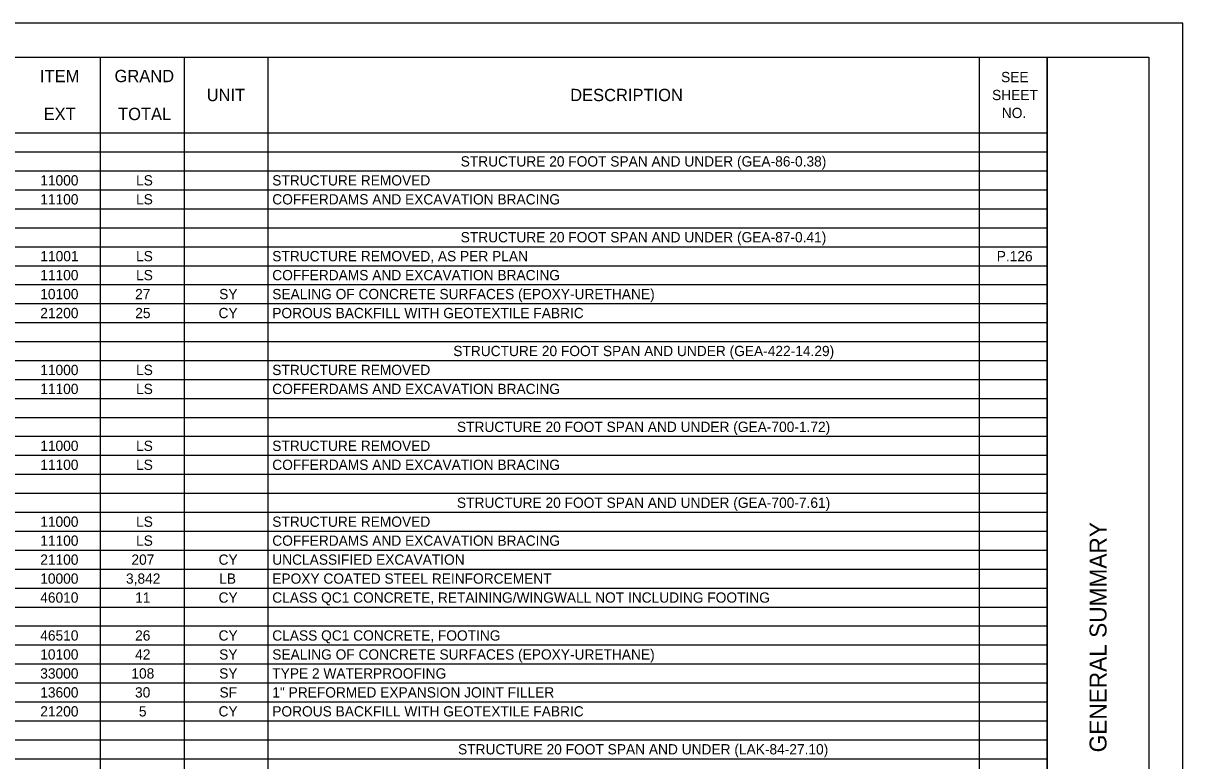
# Model space of a CAD drawing. Extents: x 0 to 34, y 0 to 22.
# Drawn here: x 16.9 to 34, y 11.11 to 22 of the extents above; entities that cross this region are included whole.
import ezdxf

# ---------------------------------------------------------------- set-up
doc = ezdxf.new("R2010")
doc.units = 0
for name, color, linetype in [('SH_Border', 7, 'Continuous'), ('SH_Cut_Line', 7, 'Continuous'), ('SH_Data', 7, 'Continuous'), ('SH_Text', 7, 'Continuous')]:
    doc.layers.add(name, color=color, linetype=linetype)

msp = doc.modelspace()

# ---------------------------------------------------------------- linework, layer by layer
at = {"layer": 'SH_Border'}
msp.add_line((32, 0.5), (32, 21.5), dxfattribs=at)
msp.add_lwpolyline([(1.5, 21.5), (33.5, 21.5), (33.5, 0.5), (1.5, 0.5)], close=True, dxfattribs=at)
at = {"layer": 'SH_Cut_Line'}
msp.add_lwpolyline([(0, 0), (34, 0), (34, 22), (0, 22)], close=True, dxfattribs=at)
at = {"layer": 'SH_Text'}
for p, q in [((1.5, 21.5), (32, 21.5)), ((18.035, 21.5), (18.035, 0.502)), ((19.27, 21.5), (19.27, 0.502)), ((20.505, 21.5), (20.505, 0.502)), ((30.995, 21.5), (30.995, 0.502)), ((32, 21.5), (32, 0.502)), ((1.5, 20.38), (32, 20.38)), ((1.5, 20.1), (32, 20.1)), ((1.5, 19.82), (32, 19.82)), ((1.5, 19.54), (32, 19.54)), ((1.5, 19.26), (32, 19.26)), ((1.5, 18.98), (32, 18.98)), ((1.5, 18.7), (32, 18.7)), ((1.5, 18.42), (32, 18.42)), ((1.5, 18.14), (32, 18.14)), ((1.5, 17.86), (32, 17.86)), ((1.5, 17.58), (32, 17.58)), ((1.5, 17.3), (32, 17.3)), ((1.5, 17.021), (32, 17.021)), ((1.5, 16.741), (32, 16.741)), ((1.5, 16.461), (32, 16.461)), ((1.5, 16.181), (32, 16.181)), ((1.5, 15.901), (32, 15.901)), ((1.5, 15.621), (32, 15.621)), ((1.5, 15.341), (32, 15.341)), ((1.5, 15.061), (32, 15.061)), ((1.5, 14.781), (32, 14.781)), ((1.5, 14.501), (32, 14.501)), ((1.5, 14.221), (32, 14.221)), ((1.5, 13.941), (32, 13.941)), ((1.5, 13.661), (32, 13.661)), ((1.5, 13.381), (32, 13.381)), ((1.5, 13.101), (32, 13.101)), ((1.5, 12.821), (32, 12.821)), ((1.5, 12.541), (32, 12.541)), ((1.5, 12.261), (32, 12.261)), ((1.5, 11.981), (32, 11.981)), ((1.5, 11.701), (32, 11.701)), ((1.5, 11.421), (32, 11.421)), ((1.5, 11.141), (32, 11.141))]:
    msp.add_line(p, q, dxfattribs=at)

# ---------------------------------------------------------------- texts
at = {"layer": 'SH_Data'}
msp.add_text('GENERAL SUMMARY', height=0.25, rotation=90, dxfattribs=at).set_placement((32.875, 11.235))
at = {"layer": 'SH_Text'}
for s, height, p in [('ITEM', 0.1818, (17.145, 21.129)), ('GRAND', 0.1818, (18.245, 21.129)), ('SEE ', 0.1515, (31.32, 21.129)), ('UNIT', 0.1818, (19.604, 20.849)), ('DESCRIPTION', 0.18181, (24.965, 20.849)), ('SHEET ', 0.1515, (31.187, 20.864)), ('EXT', 0.1818, (17.199, 20.569)), ('TOTAL', 0.1818, (18.297, 20.569)), ('NO.', 0.1515, (31.331, 20.599)), ('STRUCTURE 20 FOOT SPAN AND UNDER (GEA-86-0.38)', 0.15151, (23.35, 19.884)), ('11000', 0.1515, (17.149, 19.604)), ('LS', 0.1515, (18.562, 19.604)), ('STRUCTURE REMOVED', 0.15151, (20.571, 19.604)), ('11100', 0.1515, (17.149, 19.324)), ('LS', 0.1515, (18.562, 19.324)), ('COFFERDAMS AND EXCAVATION BRACING', 0.15151, (20.571, 19.324)), ('STRUCTURE 20 FOOT SPAN AND UNDER (GEA-87-0.41)', 0.15151, (23.35, 18.765)), ('11001', 0.1515, (17.151, 18.485)), ('LS', 0.1515, (18.562, 18.485)), ('STRUCTURE REMOVED, AS PER PLAN', 0.15151, (20.571, 18.485)), ('P.126', 0.1515, (31.256, 18.485)), ('11100', 0.1515, (17.149, 18.205)), ('LS', 0.1515, (18.562, 18.205)), ('COFFERDAMS AND EXCAVATION BRACING', 0.15151, (20.571, 18.205)), ('10100', 0.1515, (17.149, 17.925)), ('27', 0.1515, (18.548, 17.925)), ('SY', 0.1515, (19.788, 17.925)), ('SEALING OF CONCRETE SURFACES (EPOXY-URETHANE)', 0.15151, (20.571, 17.925)), ('21200', 0.1515, (17.149, 17.645)), ('25', 0.1515, (18.55, 17.645)), ('CY', 0.1515, (19.779, 17.645)), ('POROUS BACKFILL WITH GEOTEXTILE FABRIC', 0.15151, (20.571, 17.645)), ('STRUCTURE 20 FOOT SPAN AND UNDER (GEA-422-14.29)', 0.15151, (23.241, 17.085)), ('11000', 0.1515, (17.149, 16.805)), ('LS', 0.1515, (18.562, 16.805)), ('STRUCTURE REMOVED', 0.15151, (20.571, 16.805)), ('11100', 0.1515, (17.149, 16.525)), ('LS', 0.1515, (18.562, 16.525)), ('COFFERDAMS AND EXCAVATION BRACING', 0.15151, (20.571, 16.525)), ('STRUCTURE 20 FOOT SPAN AND UNDER (GEA-700-1.72)', 0.15151, (23.295, 15.965)), ('11000', 0.1515, (17.149, 15.685)), ('LS', 0.1515, (18.562, 15.685)), ('STRUCTURE REMOVED', 0.15151, (20.571, 15.685)), ('11100', 0.1515, (17.149, 15.405)), ('LS', 0.1515, (18.562, 15.405)), ('COFFERDAMS AND EXCAVATION BRACING', 0.15151, (20.571, 15.405)), ('STRUCTURE 20 FOOT SPAN AND UNDER (GEA-700-7.61)', 0.15151, (23.295, 14.845)), ('11000', 0.1515, (17.149, 14.565)), ('LS', 0.1515, (18.562, 14.565)), ('STRUCTURE REMOVED', 0.15151, (20.571, 14.565)), ('11100', 0.1515, (17.149, 14.285)), ('LS', 0.1515, (18.562, 14.285)), ('COFFERDAMS AND EXCAVATION BRACING', 0.15151, (20.571, 14.285)), ('21100', 0.1515, (17.149, 14.005)), ('207', 0.1515, (18.494, 14.005)), ('CY', 0.1515, (19.779, 14.005)), ('UNCLASSIFIED EXCAVATION', 0.15151, (20.571, 14.005)), ('10000', 0.1515, (17.149, 13.725)), ('3,842', 0.1515, (18.414, 13.725)), ('LB', 0.1515, (19.788, 13.725)), ('EPOXY COATED STEEL REINFORCEMENT', 0.15151, (20.571, 13.725)), ('46010', 0.1515, (17.149, 13.445)), ('11', 0.1515, (18.549, 13.445)), ('CY', 0.1515, (19.779, 13.445)), ('CLASS QC1 CONCRETE, RETAINING/WINGWALL NOT INCLUDING FOOTING', 0.15151, (20.571, 13.445)), ('46510', 0.1515, (17.149, 12.885)), ('26', 0.1515, (18.548, 12.885)), ('CY', 0.1515, (19.779, 12.885)), ('CLASS QC1 CONCRETE, FOOTING', 0.15151, (20.571, 12.885)), ('10100', 0.1515, (17.149, 12.605)), ('42', 0.1515, (18.549, 12.605)), ('SY', 0.1515, (19.788, 12.605)), ('SEALING OF CONCRETE SURFACES (EPOXY-URETHANE)', 0.15151, (20.571, 12.605)), ('33000', 0.1515, (17.149, 12.325)), ('108', 0.1515, (18.493, 12.325)), ('SY', 0.1515, (19.788, 12.325)), ('TYPE 2 WATERPROOFING', 0.15151, (20.571, 12.325)), ('13600', 0.1515, (17.149, 12.045)), ('30', 0.1515, (18.547, 12.045)), ('SF', 0.1515, (19.793, 12.045)), ('1" PREFORMED EXPANSION JOINT FILLER', 0.15151, (20.571, 12.045)), ('21200', 0.1515, (17.149, 11.765)), ('5', 0.152, (18.604, 11.765)), ('CY', 0.1515, (19.779, 11.765)), ('POROUS BACKFILL WITH GEOTEXTILE FABRIC', 0.15151, (20.571, 11.765)), ('STRUCTURE 20 FOOT SPAN AND UNDER (LAK-84-27.10)', 0.15151, (23.311, 11.205))]:
    msp.add_text(s, height=height, dxfattribs=at).set_placement(p)

doc.saveas('drawing.dxf')
